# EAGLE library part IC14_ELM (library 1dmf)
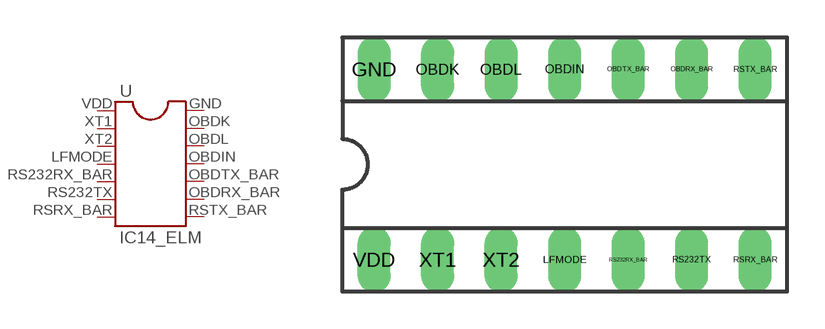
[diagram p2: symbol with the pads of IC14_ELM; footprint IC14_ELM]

Designator prefix -

## IC14_ELM1  [IC14_ELM]
GND  14  pas
LFMODE  4  pas
OBDIN  11  pas
OBDK  13  pas
OBDL  12  pas
OBDRX_BAR  9  pas
OBDTX_BAR  10  pas
RS232RX_BAR  5  pas
RS232TX  6  pas
RSRX_BAR  7  pas
RSTX_BAR  8  pas
VDD  1  pas
XT1  2  pas
XT2  3  pas

## Footprint IC14_ELM (pad centres in mm)
drill 0.813 long: GND -8.89,3.81; LFMODE -1.27,-3.81; OBDIN -1.27,3.81; OBDK -6.35,3.81; OBDL -3.81,3.81; OBDRX_BAR 3.81,3.81; OBDTX_BAR 1.27,3.81; RS232RX_BAR 1.27,-3.81; RS232TX 3.81,-3.81; RSRX_BAR 6.35,-3.81; RSTX_BAR 6.35,3.81; VDD -8.89,-3.81; XT1 -6.35,-3.81; XT2 -3.81,-3.81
